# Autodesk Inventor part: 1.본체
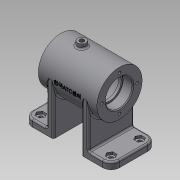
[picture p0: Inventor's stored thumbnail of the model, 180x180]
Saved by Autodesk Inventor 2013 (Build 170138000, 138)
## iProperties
Created: 2017-02
Part Number: 1.본체
Material: 일반
Document SubType Name: Modeling
Designer: hana-cad19
Density: 1 g/cm^3
Author: hana-cad19
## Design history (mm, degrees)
sketch "스케치1"
  geometry: C1 r 27 at (0, 0); 1 further point
  constraints: 1 centre point, 1 coincident
  dimensions: "d0" = 54 diameter of C1
extrude "돌출1" new body sketch "스케치1" stored distance "d2" = 70; taper "d3" = 0 deg
node "작업 평면1"
sketch "스케치2"
  geometry: L1 (-27, 0)-(-27, -60); L2 (-27, -60)-(27, -60); L3 (27, -60)-(27, 0); A1 r 27 centre (0, 0) between (-27, 0) and (27, 0) reference; 1 further point
  constraints: 6 end point, 2 point on circle, 2 tangent, 1 parallel, 1 perpendicular, 1 vertical
  dimensions: "d5" = 60 distance from line of L2 L3.end
extrude "돌출2" join sketch "스케치2" distance "d7" = 8; taper "d8" = 0 deg
node "작업 평면2"
sketch "스케치3"
  geometry: L1 (25, -60)-(25, 0) reference; L2 (25, -60)-(52, -60); L3 (52, -60)-(52, -52); L4 (52, -52)-(25, -52); 1 further point
  constraints: 6 end point, 3 perpendicular, 1 point on line
  dimensions: "d10" = 8 distance between parallel lines of L4 L2; "d12" = 52 distance from line of L3 point (0, 0)
extrude "돌출3" join sketch "스케치3" stored distance "d13" = 54; taper "d14" = 0 deg
sketch "스케치4"
  geometry: L1 (-35, 27)-(-35, -27) reference; L2 (35, -27)-(35, 27) reference; L3 (-35, 0)-(35, 0); L4 (-35, 16)-(-23.3, 16); L5 (-23, 15.7)-(-23, 14); L6 (-23, 14)-(-20, 14); L7 (-20, 14)-(-20, 19); L8 (-17, 22)-(17, 22); L9 (20, 19)-(20, 14); L10 (20, 14)-(23, 14); L11 (23, 14)-(23, 15.7); L12 (23.3, 16)-(35, 16); A1 r 3 centre (-17, 19) between (-17, 22) and (-20, 19); A2 r 3 centre (17, 19) between (20, 19) and (17, 22); A3 r 0.3 centre (-23.3, 15.7) between (-23, 15.7) and (-23.3, 16); A4 r 0.3 centre (23.3, 15.7) between (23.3, 16) and (23, 15.7); 1 further point
  constraints: 20 end point, 9 parallel, 8 point on circle, 8 tangent, 4 centre point, 2 equal radius, 2 midpoint, 2 perpendicular, 2 point on line
  dimensions: "d15" = 12 distance between parallel lines of L5 L1; "d16" = 40 distance between parallel lines of L9 L7; "d17" = 12 distance between parallel lines of L2 L11; "d18" = 3 distance between parallel lines of L7 L5; "d19" = 28 diameter of L6 L3; "d20" = 32 diameter of L4 L3; "d21" = 44 diameter of L8 L3; "d22" = 3 radius of A1; "d23" = 0.3 radius of A3
revolve "회전1" sketch "스케치4" stored, may be unused: angle "d24" = 90 deg
sketch "스케치5"
  geometry: C1 r 16 at (0, 0) reference; 1 further point
  constraints: 1 horizontal alignment
  dimensions: "d25" = 21 distance of C1.centre point (-21, 0)
hole "구멍1" sketch "스케치5" at (-21, 0) diameter "d26" = 3.242; stored, may be unused: countersink angle "d30" = 90 deg, drill point angle "d32" = 118 deg; dims "d27" = 8, "d28" = 4, "d29" = 2, "d31" = 10
node "작업 평면3"
sketch "스케치6"
  geometry: L1 (-35, 27)-(-35, -27) reference; C1 r 5 at (-10, 0); 1 further point
  constraints: 1 centre point, 1 horizontal alignment
  dimensions: "d37" = 10 diameter of C1; "d39" = 25 distance from line of C1.centre L1
extrude "돌출4" join sketch "스케치6" stored distance "d40" = 54; taper "d41" = 0 deg
sketch "스케치7"
  geometry: C1 r 5 at (0, 0) reference; 1 further point
hole "구멍2" sketch "스케치7" at (0, 0) diameter "d42" = 5.188; stored, may be unused: countersink angle "d46" = 90 deg, drill point angle "d48" = 118 deg; dims "d43" = 8, "d44" = 4, "d45" = 2, "d47" = 10
sketch "스케치8"
  geometry: L1 (0, 0)-(0, -27); L2 (0, 0)-(16.339, -25.16); L3 (16.339, -25.16)-(11.307, -28.428); L4 (11.307, -28.428)-(8.039, -23.396); L5 (8.039, -23.396)-(13.071, -20.128); A1 r 27 centre (0, 0) between (-27, 0) and (27, 0) reference; 1 further point
  constraints: 10 end point, 3 perpendicular, 1 point on circle, 1 point on line
  dimensions: "d49" = 12 diameter of L4 L2; "d51" = 33 deg angle of L2 L1; "d53" = 30 distance of L2.end point (0, 0); "d54" = 6 distance between parallel lines of L3 L5
revolve "회전2" sketch "스케치8" stored, may be unused: angle "d55" = 90 deg
sketch "스케치9"
  geometry: C1 r 6 at (0, 0) reference
hole "구멍3" sketch "스케치9" at (0, 0) diameter "d56" = 5.188; stored, may be unused: countersink angle "d60" = 90 deg, drill point angle "d62" = 118 deg; dims "d57" = 8, "d58" = 4, "d59" = 2, "d61" = 10
chamfer "모따기1" distance "d63" = 1; stored, may be unused: second distance "d64" = 2, angle "d65" = 45 deg
sketch "스케치10" dims "d69" = 9
  geometry: L1 (-50, 0)-(-50, 54) reference; L2 (-77, 54)-(-50, 54) reference; L3 (-77, 0)-(-77, 54) reference; L4 (-50, 0)-(-77, 0) reference; L5 (-42, 0)-(-50, 0) reference; L6 (-42, 54)-(-42, 0) reference; L7 (-50, 54)-(-42, 54) reference; L8 (0, 54)-(0, 0) reference; L9 (27, 0)-(0, 0) reference; L10 (27, 54)-(27, 0) reference; L11 (0, 54)-(27, 54) reference; L12 (-8, 54)-(0, 54) reference; L13 (-8, 0)-(-8, 54) reference; L14 (0, 0)-(-8, 0) reference; L15 (-67, 10)-(17, 10); L16 (17, 10)-(17, 44); L17 (17, 44)-(-67, 44); L18 (-67, 44)-(-67, 10); L19 (-67, 10)-(17, 44); L20 (17, 10)-(-67, 44); L21 (14.402, 39.5)-(11.804, 44); L22 (11.804, 44)-(14.402, 48.5); L23 (14.402, 48.5)-(19.598, 48.5); L24 (19.598, 48.5)-(22.196, 44); L25 (22.196, 44)-(19.598, 39.5); L26 (19.598, 39.5)-(14.402, 39.5); 4 further points
  constraints: 24 end point, 3 midpoint, 2 coincident, 2 parallel, 1 horizontal, 1 horizontal alignment, 1 perpendicular, 1 vertical alignment, 15 other
  dimensions: "d66" = 84 distance between parallel lines of L16 L18; "d68" = 34 distance between parallel lines of L15 L17
extrude "돌출5" cut sketch "스케치10" distance "d70" = 3; taper "d71" = 0 deg
sketch "스케치11"
  geometry: L1 (14.402, 48.5)-(19.598, 48.5) reference; C1 r 2.5 at (17, 44); 3 further points
  constraints: 1 centre point, 1 horizontal alignment, 1 midpoint, 1 vertical alignment
  dimensions: "d72" = 5 diameter of C1
extrude "돌출6" cut sketch "스케치11" stored distance "d74" = 3; taper "d75" = 0 deg
fillet "모깎기1" dims "d76" = 10
fillet "모깎기2" dims "d77" = 2
fillet "모깎기3" dims "d78" = 2
fillet "모깎기4" dims "d79" = 2
fillet "모깎기5" dims "d80" = 2
fillet "모깎기6" dims "d81" = 2
fillet "모깎기7" dims "d82" = 2
node "작업 평면4"
sketch "스케치12"
  geometry: L1 (-35, 27)-(-35, -27) reference; L2 (-35, 27)-(35, 27) reference; 2 further points
  constraints: 1 other
  dimensions: "d84" = 35 distance from line of point (0, 0) L1; "d85" = 27 distance from line of L2 point (0, 0)
feature "엠보싱1" sketch "스케치12" dims "d86" = 0.5, "d87" = 0
node "솔리드1"
mirror "대칭1"
pattern_circular "원형 패턴1" dims angle "d34" = 360 deg
mirror "대칭2"
mirror "대칭3"
mirror "대칭4"
node "절단 모서리 투영1"
other parameters: "d4" = 17, "d9" = 90 deg, "d36" = 32
